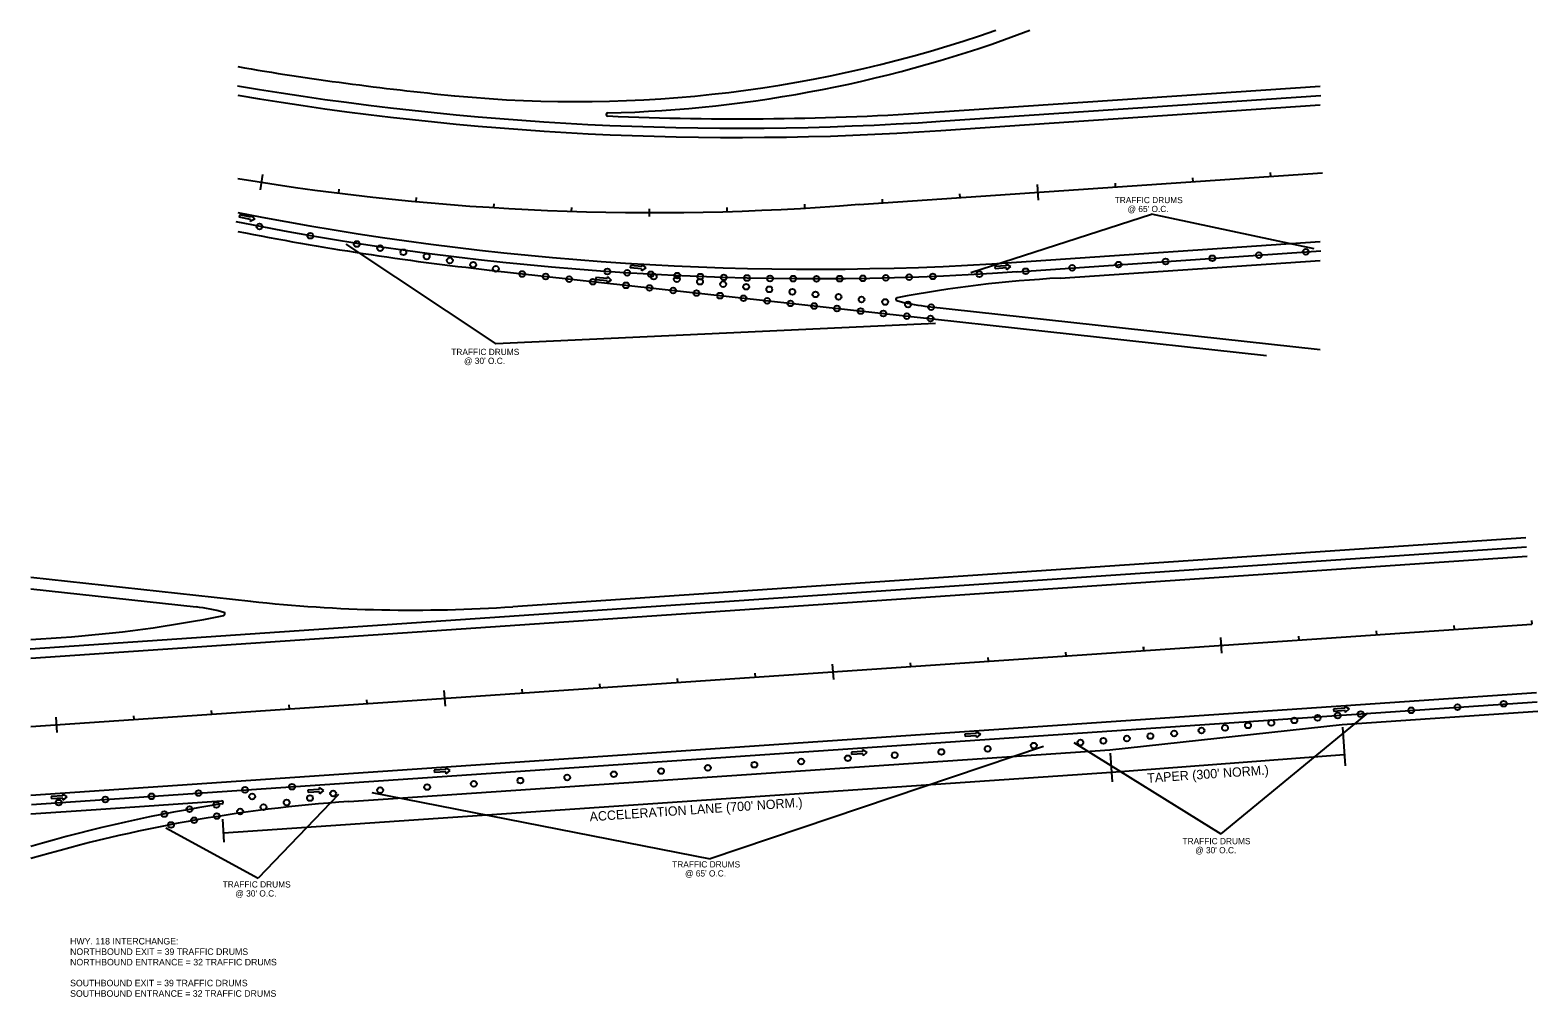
# Model space of a CAD drawing. Extents: x 13528 to 25043, y 7635 to 10612.
# Drawn here: x 22020 to 23403, y 7635 to 8522 of the extents above; entities that cross this region are included whole.
import ezdxf

# ---------------------------------------------------------------- set-up
doc = ezdxf.new("R2010")
doc.units = 0
for name, color, linetype in [('Default', 7, 'Continuous'), ('R_Border', 7, 'Continuous'), ('STAMP_PE_TAEGTMEYER', 7, 'Continuous')]:
    doc.layers.add(name, color=color, linetype=linetype)

# ---------------------------------------------------------------- blocks, each defined once
blk = doc.blocks.new('DOT')
at = {"layer": 'Default'}
blk.add_circle((-0.4, -0.3), 3.75, dxfattribs=at)
blk = doc.blocks.new('SARROW')
at = {"layer": 'Default'}
for p, q in [((15.6, 3.2), (-13.8, 3.2)), ((-13.8, 3.2), (-13.8, -2.8)), ((15.6, 8.2), (15.6, 3.2)), ((15.6, 8.2), (26, 0.2)), ((26, 0.2), (15.6, -7.8)), ((15.6, -2.8), (-13.8, -2.8)), ((15.6, -2.8), (15.6, -7.8))]:
    blk.add_line(p, q, dxfattribs=at)

msp = doc.modelspace()

# ---------------------------------------------------------------- linework, layer by layer
at = {"layer": 'Default'}
for p, q in [((22854.3, 8447.4), (23203.6, 8471.2)), ((22854.9, 8438.8), (23204.1, 8462.6)), ((22855.5, 8430.3), (23203.6, 8454)), ((22780.3, 8362.5), (23205.7, 8391.4)), ((22924.8, 8309.4), (23203.6, 8328.4)), ((22925.3, 8300.8), (23204.1, 8319.8)), ((22441, 8302.3), (23154.4, 8224)), ((22964.9, 8294.9), (23203.6, 8311.2)), ((22840.6, 8269.2), (23203.6, 8229.4)), ((22462.8, 7993.4), (23392.4, 8056.7)), ((22019.7, 7954.6), (23393, 8048.2)), ((22020.3, 7946), (23393.6, 8039.6)), ((22020.3, 8020.5), (22222.1, 7998.3)), ((22020.3, 8009.7), (22172, 7993.1)), ((22020.3, 7883.3), (23397.9, 7977.2)), ((22020.3, 7963.2), (22048.3, 7965.1)), ((22020.3, 7820.4), (23402.1, 7914.6)), ((22020.9, 7811.9), (23402.7, 7906.1)), ((23223.8, 7885.3), (23403.3, 7897.5)), ((23010.4, 7862.1), (23223.8, 7885.3)), ((23223.9, 7882.9), (23226.4, 7847.3)), ((22312.2, 7814.5), (23010.4, 7862.1)), ((23010.8, 7858.9), (23012.6, 7832.7)), ((22197.3, 7785.8), (23012, 7841.4)), ((22020.3, 7803.2), (22080.2, 7807.3)), ((22080.2, 7807.3), (22195.3, 7815.2)), ((22197.9, 7777.1), (22196.5, 7798.2))]:
    msp.add_line(p, q, dxfattribs=at)
for points in [[(22233.1, 8389.9), (22230.9, 8375.8)], [(23086.5, 8386.9), (23086.8, 8383.3)], [(23157.8, 8391.8), (23158, 8388.2)], [(22303.1, 8376.5), (22302.7, 8372.9)], [(22872.7, 8372.3), (22873, 8368.8)], [(22943.8, 8380.8), (22944.7, 8366.5)], [(23015.3, 8382), (23015.5, 8378.5)], [(22374, 8368.8), (22373.7, 8365.2)], [(22445.1, 8363.2), (22444.9, 8359.6)], [(22516.4, 8359.8), (22516.3, 8356.2)], [(22587.7, 8358.6), (22587.7, 8351.5)], [(22659, 8359.6), (22659.1, 8356)], [(22730.2, 8362.7), (22730.4, 8359.1)], [(22801.5, 8367.5), (22801.7, 8363.9)], [(23254.9, 7971.1), (23255.1, 7967.5)], [(23326.1, 7976), (23326.4, 7972.4)], [(23397.4, 7980.8), (23397.7, 7977.2)], [(23041.1, 7956.5), (23041.3, 7952.9)], [(23041.3, 7956.5), (23041.5, 7953)], [(23112.1, 7964.9), (23113.1, 7950.7)], [(23112.4, 7961.4), (23112.6, 7957.8)], [(23183.6, 7966.2), (23183.9, 7962.7)], [(22827.3, 7941.9), (22827.6, 7938.4)], [(22898.6, 7946.8), (22898.8, 7943.2)], [(22969.8, 7951.6), (22970.1, 7948.1)], [(22684.8, 7932.2), (22685, 7928.6)], [(22755.8, 7940.6), (22756.8, 7926.4)], [(22399.5, 7916.3), (22400.5, 7902.1)], [(22471, 7917.6), (22471.2, 7914.1)], [(22542.3, 7922.5), (22542.5, 7918.9)], [(22613.5, 7927.3), (22613.8, 7923.8)], [(22257.2, 7903.1), (22257.4, 7899.5)], [(22328.5, 7907.9), (22328.7, 7904.4)], [(22043.2, 7892), (22044.1, 7877.8)], [(22114.7, 7893.3), (22114.9, 7889.8)], [(22185.9, 7898.2), (22186.2, 7894.6)]]:
    msp.add_lwpolyline(points, dxfattribs=at)
for centre, radius, start, end in [((22520.8, 9620.8), 1163.9, 264.517, 289.3234), ((22520.8, 9620.8), 1174.7, 271.4149, 290.7624), ((22669.3, 11160.9), 2711.1, 260.2498, 264.4954), ((22669.3, 11160.9), 2728.4, 260.3121, 273.9), ((22669.3, 11160.9), 2736.9, 260.3428, 273.9), ((22549.8, 8445.1), 1.43, 91.4149, 267.4796), ((22669.3, 11160.9), 2719.8, 267.4796, 273.9), ((22591.7, 10693.6), 2338.6, 260.6122, 274.6268), ((22739.8, 11022.9), 2728.4, 258.7725, 273.9002), ((22739.8, 11022.9), 2719.8, 258.7725, 273.9002), ((22739.8, 11022.9), 2736.9, 258.8438, 263.7365), ((23024.6, 7166.6), 1129.9, 93.0271, 100.6758), ((22815.5, 8275.6), 1.43, 101.3026, 252.2444), ((22857.6, 8423.9), 155.6, 254.1488, 263.766), ((22370.4, 9349), 1358.8, 263.7335, 273.9), ((21971.6, 9092.7), 1130.2, 273.8913, 281.5292), ((22155.1, 7838.6), 155.4, 74.1663, 83.7815), ((22197.1, 7986.7), 1.43, 282.7091, 74.1562), ((22404.7, 6458.8), 1358.8, 93.9033, 106.4326), ((22404.7, 6458.8), 1369.5, 98.7808, 106.3005), ((22195.4, 7813.7), 1.43, 278.7808, 93.9002)]:
    msp.add_arc(centre, radius, start, end, dxfattribs=at)
at = {"layer": 'R_Border'}
for p, q in [((22883.1, 8300.1), (23048.8, 8353.5)), ((23197.9, 8321.7), (23048.8, 8353.5)), ((22309.4, 8326.2), (22447.1, 8234.6)), ((22850.6, 8253.3), (22447.1, 8234.6)), ((23247.1, 7895.5), (23112.3, 7784.8)), ((22949.7, 7864.9), (22643.8, 7761.8)), ((22977.6, 7868.6), (23112.3, 7784.8)), ((23012, 7841.4), (23225.7, 7857.8)), ((22302.8, 7821), (22228.9, 7744.3)), ((22333.2, 7822.9), (22643.8, 7761.8)), ((22144.2, 7790.5), (22228.9, 7744.3))]:
    msp.add_line(p, q, dxfattribs=at)

# ---------------------------------------------------------------- block references
for p, xscale, yscale, rotation in [((22216.7, 8350.8), 0.3571428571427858, 0.3571428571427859, -11.39868897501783), ((22575.4, 8304.9), 0.3571428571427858, 0.3571428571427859, -4.719167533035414), ((22910, 8304.8), 0.3571428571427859, 0.3571428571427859, 3.86313464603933), ((22543.7, 8293.9), 0.3571428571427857, 0.35714285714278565, -5.7638927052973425), ((23220.8, 7898.6), 0.3571428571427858, 0.35714285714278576, 4.736555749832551), ((22882.5, 7875.6), 0.3571428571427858, 0.35714285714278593, 3.216567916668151), ((22778.3, 7858.9), 0.3571428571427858, 0.35714285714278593, 3.216567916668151), ((22395.6, 7842.4), 0.3571428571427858, 0.35714285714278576, 3.755097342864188), ((22044.1, 7818.2), 0.3571428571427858, 0.3571428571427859, 3.43151276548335), ((22279.6, 7824), 0.3571428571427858, 0.35714285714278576, 3.755097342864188)]:
    msp.add_blockref('SARROW', p, dxfattribs=dict(at, xscale=xscale, yscale=yscale, rotation=rotation))
at = {"layer": 'R_Border', "xscale": 0.7142857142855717, "yscale": 0.7142857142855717}
for p in [(22230.4, 8342.5), (22277.1, 8334), (22319.8, 8326.4), (22341.2, 8322.6), (22362.5, 8318.8), (22383.9, 8315), (23104.9, 8313.3), (23147.5, 8316.2), (23190.6, 8319.2), (22405.2, 8311.2), (22426.6, 8307.4), (22447.4, 8303.7), (22471.6, 8298.9), (22549.7, 8301.1), (22567.8, 8300), (22933.6, 8301.4), (22976.2, 8304.6), (23018.7, 8307.5), (23062, 8310.4), (22493.1, 8296.6), (22514.7, 8294.2), (22536.3, 8291.8), (22566.8, 8288.5), (22588.4, 8286.1), (22589.6, 8298.6), (22592.2, 8296.5), (22613.5, 8294.1), (22613.7, 8297.4), (22634.7, 8291.8), (22635, 8296.5), (22655.9, 8289.5), (22656.5, 8295.8), (22677.1, 8287.2), (22677.8, 8295.2), (22699, 8294.8), (22720.2, 8294.6), (22741.6, 8294.5), (22762.9, 8294.6), (22784.1, 8294.9), (22805.3, 8295.3), (22826.7, 8295.9), (22848.4, 8296.7), (22891.1, 8298.7), (22610, 8283.7), (22631.5, 8281.4), (22653.1, 8279), (22674.7, 8276.6), (22696.3, 8274.3), (22698.3, 8284.8), (22717.8, 8271.9), (22719.5, 8282.5), (22740.7, 8280.2), (22761.9, 8277.9), (22783, 8275.5), (22804.6, 8273.2), (22739.4, 8269.5), (22760.4, 8267.2), (22782.1, 8264.9), (22803, 8262.6), (22824.6, 8260.2), (22825.6, 8270.9), (22846.2, 8258), (22846.8, 8268.5), (23287.3, 7898.4), (23329.8, 7901.4), (23372.2, 7904.5), (23137.6, 7884.6), (23159, 7886.9), (23180.1, 7889.2), (23201.5, 7891.5), (23219.9, 7893.6), (23241, 7895), (23004.9, 7870.4), (23026.5, 7872.5), (23048, 7874.8), (23069.8, 7877.2), (23095, 7879.9), (23116.5, 7882.3), (22813.4, 7857.3), (22856.2, 7860.2), (22898.7, 7863.1), (22941.1, 7866), (22983.8, 7868.9), (22599, 7842.7), (22641.9, 7845.6), (22684.6, 7848.5), (22727.5, 7851.4), (22770.4, 7854.4), (22427.1, 7830.9), (22469.9, 7833.9), (22512.9, 7836.8), (22555.6, 7839.7), (22089, 7816.6), (22131.3, 7819.5), (22174.6, 7822.5), (22217.2, 7825.4), (22223.7, 7819.4), (22260.3, 7828.3), (22276.8, 7817.9), (22298.1, 7822.1), (22341.2, 7825.1), (22384.3, 7828), (22046.2, 7813.7), (22143.2, 7803.2), (22166.2, 7807.7), (22190.9, 7811.6), (22191.3, 7801.4), (22212.7, 7805.5), (22234.1, 7809.6), (22255.4, 7813.8), (22149.3, 7793.2), (22170.5, 7797.5)]:
    msp.add_blockref('DOT', p, dxfattribs=at)

# ---------------------------------------------------------------- texts
at = {"layer": 'Default'}
for s, rotation, p in [("TAPER (300' NORM.)", 3.9033, (23045.1, 7831.7)), ("ACCELERATION LANE (700' NORM.)", 3.9032, (22533.4, 7796.3))]:
    msp.add_text(s, height=8.571, rotation=rotation, dxfattribs=at).set_placement(p)
at = {"layer": 'R_Border'}
for s, height, p in [('TRAFFIC DRUMS ', 5.714, (23015, 8363.7)), ("@ 65' O.C.", 5.71, (23026.8, 8355.5)), ('TRAFFIC DRUMS ', 5.714, (22406.2, 8224.3)), ("@ 30' O.C.", 5.71, (22417.9, 8216.1)), ('TRAFFIC DRUMS ', 5.714, (23077.2, 7775.3)), ("@ 30' O.C.", 5.71, (23088.9, 7767)), ('TRAFFIC DRUMS ', 5.714, (22608.9, 7754)), ("@ 65' O.C.", 5.71, (22620.7, 7745.7)), ('TRAFFIC DRUMS ', 5.714, (22196.4, 7735.6)), ("@ 30' O.C.", 5.71, (22208.1, 7727.3))]:
    msp.add_text(s, height=height, dxfattribs=at).set_placement(p)
at = {"layer": 'STAMP_PE_TAEGTMEYER'}
for s, p in [('HWY. 118 INTERCHANGE:', (22056.4, 7683.3)), ('NORTHBOUND EXIT = 39 TRAFFIC DRUMS', (22056.4, 7673.7)), ('NORTHBOUND ENTRANCE = 32 TRAFFIC DRUMS', (22056.4, 7664.1)), ('SOUTHBOUND EXIT = 39 TRAFFIC DRUMS', (22056.4, 7644.9)), ('SOUTHBOUND ENTRANCE = 32 TRAFFIC DRUMS', (22056.4, 7635.3))]:
    msp.add_text(s, height=6, dxfattribs=at).set_placement(p)

doc.saveas('drawing.dxf')
